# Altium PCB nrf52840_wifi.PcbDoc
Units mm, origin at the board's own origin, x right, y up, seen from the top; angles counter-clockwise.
Board outline 56.97 x 18.44 mm, 2 copper layers (Top Layer, Bottom Layer), stack 0.325 mm thick; 26 components, 63 nets, 152 pads, 96 vias.
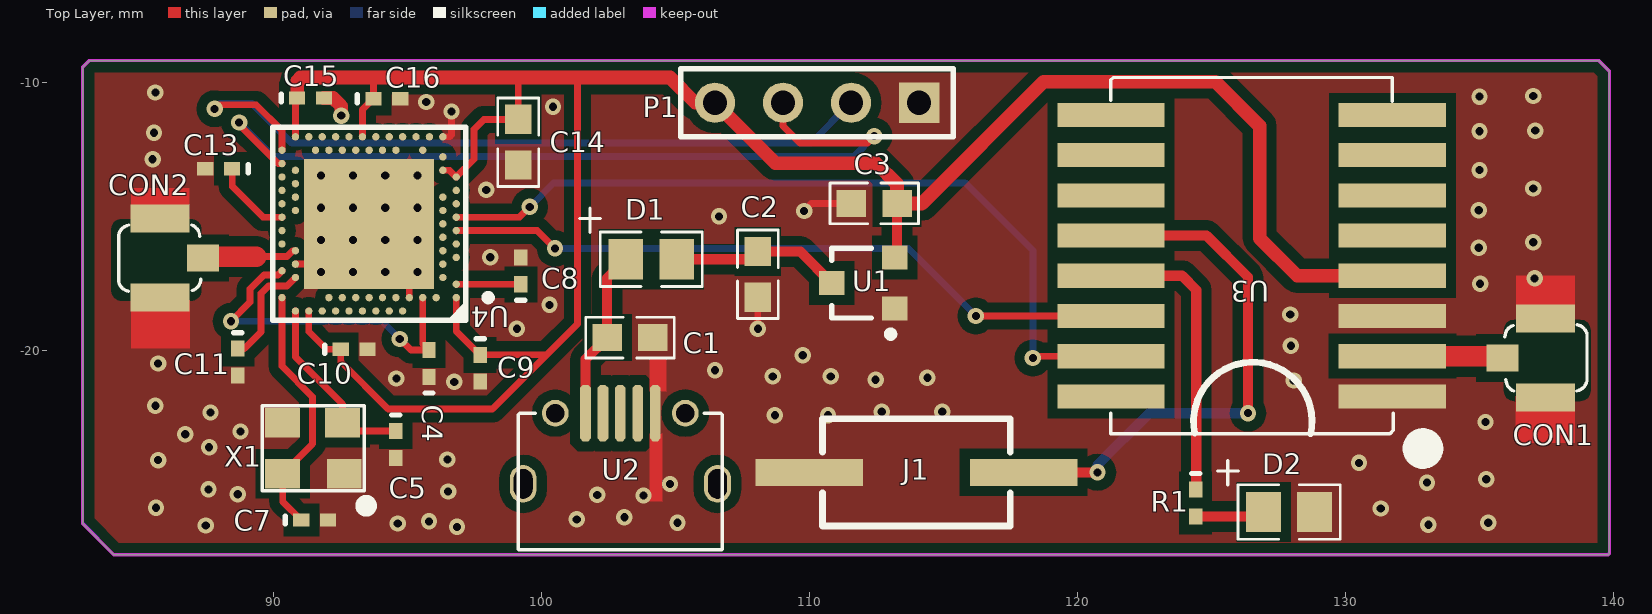
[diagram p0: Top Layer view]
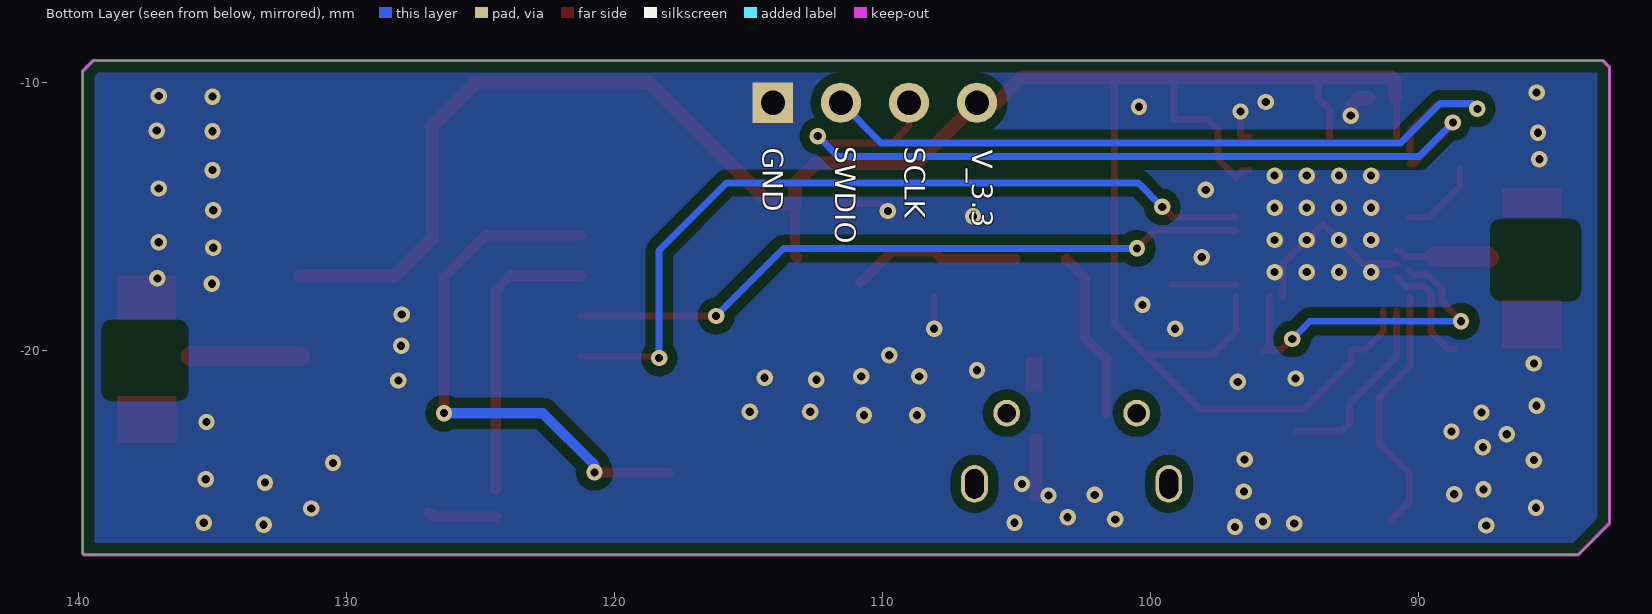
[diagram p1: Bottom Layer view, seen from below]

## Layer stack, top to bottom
Top Layer: signal copper 0.0356
Dielectric: core 0.254, FR-4, Dk 4.2
Bottom Layer: signal copper 0.0356

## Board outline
82.88,-26.441 82.88,-9.423 83.134,-9.169 139.446,-9.169 139.852,-9.576 139.852,-27.559 139.802,-27.61 84.049,-27.61

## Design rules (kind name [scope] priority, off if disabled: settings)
Clearance [All] p1: gap=0.152
ComponentClearance [All] p1 off: gap=0.254 collisioncheckmode=3 verticalgap=0.254 showdistances=FALSE
Height [All] p1 off: minheight=0 maxheight=25.4 prefheight=12.7
MinimumSolderMaskSliver [All] p1 off: minsoldermaskwidth=0.254
NetAntennae [All] p1 off: netantennaetolerance=0
PlaneConnect [All] p1: planeconnectstyle=Direct reliefexpansion=0.508 reliefentries=4 reliefconductorwidth=0.254 reliefairgap=0.254
PolygonConnect [All] p1: connectstyle=Direct reliefconductorwidth=0.254 reliefentries=4 polygonreliefangle="90 Angle"
RoutingVias [All] p1: holewidth=0.711 width=1.27 viastyle="Through Hole" minholewidth=0.711 minwidth=1.27 maxholewidth=0.711 maxwidth=1.27
SilkToSilkClearance [All] p1 off: silktosilkclearance=0.254
SilkscreenOverComponentPads SilkToSolderMaskClearance [IsPad] p1 off: minsilkscreentomaskgap=0.254
SolderMaskExpansion [All] p1: expansion=0.102
Width [All] p1: maxlimit=2.54 minlimit=0.025 preferedwidth=0.254 minimp=50.000000 maximp=50.000000 favimp=50.000000
21 further rules are at their usual default settings.

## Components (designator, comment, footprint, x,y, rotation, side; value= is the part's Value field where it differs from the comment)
C1 "2.2uF" 0603-1 103.302,-19.507 r0 top
C2 "1uF" 0603-1 108.077,-17.145 r270 top
C3 "1uF" 0603-1 112.42,-14.503 r180 top
C4 "1.0μF" 0402-A 95.809,-20.472 r90 top
C5 "12pF" 0402-A 94.564,-23.495 r270 top
C7 "12pF" 0402-A 91.542,-26.314 r0 top
C8 "100nF" 0402-A 99.238,-17.018 r90 top
C9 "1.0μF" 0402-A 97.714,-20.65 r270 top
C10 "100nF" 0402-A 93.015,-19.939 r0 top
C11 "100pF" 0402-A 88.671,-20.422 r270 top
C13 "820pF" 0402-A 87.96,-13.208 r180 top
C14 "4.7μF" 0603-1 99.136,-12.217 r270 top
C15 "100nF" 0402-a 91.389,-10.566 r0 top
C16 "100nF" 0402-a 94.234,-10.592 r0 top
CON1 "SMA/UFLR" IPX_U.FL 137.465,-20.269 r180 top
CON2 "SMA/UFLR" IPX_U.FL 85.776,-16.535 r0 top
D1 "Diode 1N4148" 0805-1 103.149,-16.586 r0 top
D2 "LED/RED" 0805-1 126.949,-26.01 r0 top
J1 "KEY" BUTTON_1 113.995,-24.536 r0 top
P1 "Header 4" HDR1X4 114.097,-10.744 r180 top
R1 "500R" 0402-a 124.409,-25.679 r270 top
U1 "MCP1703" SOT-23 112.014,-17.475 r90 top
U2 "USB_Micro" usb_micro 102.946,-22.327 r180 top
U3 "HC-25_wifi" HC-25 131.75,-11.201 r180 top
U4 "nRF52840-QIAA" AQFN50P700X700X85_HS-74N 93.574,-15.265 r180 top
X1 "32MHz" SMD3225 90.348,-24.587 r0 top

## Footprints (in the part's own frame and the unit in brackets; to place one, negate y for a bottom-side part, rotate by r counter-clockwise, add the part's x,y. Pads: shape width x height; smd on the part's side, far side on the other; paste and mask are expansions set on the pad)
0402-A [mm] "Chip Inductor; Body 1 x 0.5 mm (LxW typ)"
  rect 0.6x0.5 smd: 1(-0.5,0) 2(0.5,0)
  silkscreen extent -1.1,-0.15 -1.1,0.15
0402-a [mm] "Chip Inductor; Body 1 x 0.5 mm (LxW typ)"
  rect 0.6x0.5 smd: 1(-0.5,0) 2(0.5,0)
  silkscreen extent -1.1,-0.15 -1.1,0.15
0603-1 [mm]
  rect 1.1x1 smd: 1(-0.85,0) 2(0.85,0)
  silkscreen extent -1.65,-0.76 1.65,0.76, body extent -1.14,-0.38 1.14,0.38, height 1
0805-1 [mm]
  rect 1.3x1.5 smd: 1(0,0) 2(1.9,0)
  silkscreen extent -1.72,-1.02 2.85,1.91
AQFN50P700X700X85_HS-74N [mm]
  rect 4.85x4.85 smd mask+0.05: 74(0,0)
  round 0.275 smd paste+0.012 mask+0.05: A8(-1.25,3.25) A10(-0.75,3.25) A12(-0.25,3.25) A14(0.25,3.25) A16(0.75,3.25) A18(1.25,3.25) A20(1.75,3.25) A22(2.25,3.25) A23(2.75,3.25) AA24(3.25,-2.25) AB2(-2.75,-2.5) AC5(-2,-2.75) AC9(-1,-2.75) AC11(-0.5,-2.75) AC13(0,-2.75) AC15(0.5,-2.75) AC17(1,-2.75) AC19(1.5,-2.75) AC21(2,-2.75) AC24(3.25,-2.75) AD2(-2.75,-3.25) AD4(-2.25,-3.25) AD6(-1.75,-3.25) AD8(-1.25,-3.25) AD10(-0.75,-3.25) AD12(-0.25,-3.25) AD14(0.25,-3.25) AD16(0.75,-3.25) AD18(1.25,-3.25) AD20(1.75,-3.25) AD22(2.25,-3.25) AD23(2.75,-3.25) B1(-3.25,2.75) B3(-2.5,2.75) B5(-2,2.75) B7(-1.5,2.75) B9(-1,2.75) B11(-0.5,2.75) B13(0,2.75) B15(0.5,2.75) B17(1,2.75) B19(1.5,2.75) B24(3.25,2.75) C1(-3.25,2.25) D2(-2.75,2) D23(2.75,2) E24(3.25,1.75) F2(-2.75,1.5) F23(2.75,1.5) G1(-3.25,1.25) H2(-2.75,1) H23(2.75,1) J1(-3.25,0.75) J24(3.25,0.75) K2(-2.75,0.5) L1(-3.25,0.25) L24(3.25,0.25) M2(-2.75,0) N1(-3.25,-0.25) N24(3.25,-0.25) P2(-2.75,-0.5) P23(2.75,-0.5) R1(-3.25,-0.75) R24(3.25,-0.75) T2(-2.75,-1) T23(2.75,-1) U1(-3.25,-1.25) U24(3.25,-1.25) V23(2.75,-1.5) W1(-3.25,-1.75) W24(3.25,-1.75) Y2(-2.75,-2) Y23(2.75,-2)
  silkscreen extent -4.57,-3.6 3.6,3.6, body extent -3.55,-3.55 3.55,3.55, height 0.85
BUTTON_1 [mm]
  rect 4x1 smd: 1(-4,0) 2(4,0)
  silkscreen extent -3.5,-2 3.5,2
HC-25 [mm]
  rect 4x0.9 smd: 1(0,10.5) 2(0,9) 3(0,7.5) 4(0,6) 5(0,4.5) 6(0,3) 7(0,1.5) 8(0,0) 9(10.5,0) 10(10.5,1.5) 11(10.5,3) 12(10.5,4.5) 13(10.5,6) 14(10.5,7.5) 15(10.5,9) 16(10.5,10.5)
  silkscreen extent -1.5,-1.4 10.5,12.8
HDR1X4 [mm] "Connector; Header; 4 Position"
  rect 1.5x1.5 hole 0.9: 1(0,0)
  round 1.5 hole 0.9: 2(2.54,0) 3(5.08,0) 4(7.62,0)
  silkscreen extent -1.27,-1.27 8.89,1.27
IPX_U.FL [mm]
  rect 1.2x1 smd: 1(1.6,0)
  rect 2.2x1.05 smd: 2(0,-1.475) 3(0,1.475)
  silkscreen extent -1.55,-1.24 1.51,1.23
SMD3225 [mm]
  rect 1.3x1.1 smd: 1(0,0) 2(2.3,0) 3(2.23,1.9) 4(0,1.9)
  silkscreen extent -0.76,-1.32 3.24,2.54
SOT-23 [mm]
  rect 0.9x0.95 smd: 1(-0.95,-1.175) 2(0.95,-1.175) 3(0,1.175)
  silkscreen extent -2.03,-1.14 1.3,1.18
usb_micro [mm] "USB方?"
  oval 1x1.4 hole 0.7 slot 1.1 at 90 deg: 0(-3.625,2.638) 0(3.625,2.638)
  round 1 hole 0.7: 0(-2.425,0) 0(2.425,0)
  oct 0.4x2.1 smd: 1(1.3,0) 2(0.65,0) 3(0,0) 4(-0.65,0) 5(-1.3,0)
  silkscreen extent -3.81,0 3.81,5.1

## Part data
C1 C2 C3: library part CAP-0.1UF, "SMD-"
C4 C9: library part C0603-1?, "Capacitor, X7R, ±10%"
C5 C7: library part C0402-12p, "Capacitor, NP0, ±2%"
C8 C10 C15 C16: library part C0402-100n, "Capacitor, X7R, ±10%"
C11: library part C0402-100p, "Capacitor, NP0, ±5%"
C13: library part C0402-820p, "Capacitor, NP0, ±5%"
C14: library part C0603-4μ7-6.3, "Capacitor, X7R, ±10%"
D1: "High Conductance Fast Diode"
D2: library part LED/0603
P1: "Header, 4-Pin"
R1: library part R
U1: library part MCP170
U4: library part nRF52840-QIAAD0, "Multi-protocol Bluetooth Low Energy, IEEE 802.15.4, ANT and 2.4GHz proprietary system-on-chip"
X1: library part XTAL_SMD2016_32MHz_8pF_General, "XTAL SMD 2016, 32MHz, Cl=8pF, Total Tol: ±40ppm"

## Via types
v1: diameter 0.61, hole 0.305, Top Layer to Bottom Layer, 96 vias

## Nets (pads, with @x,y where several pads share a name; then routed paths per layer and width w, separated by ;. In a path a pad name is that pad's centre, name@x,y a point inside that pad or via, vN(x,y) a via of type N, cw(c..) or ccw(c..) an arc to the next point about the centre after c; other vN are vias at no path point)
DEC1: C8.1 U4.C1 | length 2.4
  Top Layer w0.254: U4.C1 C8.1@99.235,-17.515
DEC3: C11.1 U4.D23 | length 4.1
  Top Layer w0.254: C11.1 88.917,-19.922 89.535,-19.304 89.535,-17.856 89.814,-17.577 90.512,-17.577 U4.D23
DEC4_6: C4.2 U4.B5 U4.E24 | length 12.9
  Top Layer w0.254: v1(88.417,-18.898) 89.129,-18.186 89.129,-17.688 89.646,-17.17 90.169,-17.17 U4.E24 ; v1(94.717,-19.558) 95.131,-19.972 C4.2 95.574,-19.737 U4.B5
  Bottom Layer w0.254: v1(88.417,-18.898) 94.056,-18.898 v1(94.717,-19.558)
GND: C1.2 C2.2 C3.2 C4.1 C5.2 C7.2 C8.2 C9.2 C10.2 C11.2 C13.2 C14.2 C15.2 C16.2 CON1.2 CON1.3 CON2.2 CON2.3 D2.2 J1.1 P1.1 U1.1 U2.5 U3.1 U3.3 U4.74 U4.AD2 U4.B7 U4.F23 X1.2 X1.4 | length 12.2
  Top Layer w0.254: U4.F23 92.074,-16.765 v1(92.974,-15.865) U4.74 95.074,-16.765 U4.B7 ; U4.AD2 96.57,-12.015 96.647,-11.938 v1(96.647,-11.074) ; v1(108.077,-19.177) C2.2 ; v1(109.804,-14.783) 110.084,-14.503 C3.2
  Top Layer w0.508: C15.2 92.227,-10.566 92.532,-10.871 v1(92.532,-11.227)
  other v1: 96.85,-26.568 87.478,-26.518 133.096,-26.492 94.64,-26.441 105.08,-26.416 135.331,-26.416 95.809,-26.365 101.321,-26.289 103.099,-26.213 131.318,-25.883 85.623,-25.857 103.81,-25.4 102.083,-25.375 88.671,-25.349 96.52,-25.248 87.579,-25.171 104.8,-24.968 133.045,-24.917 135.255,-24.79 130.505,-24.181 85.7,-24.079 96.495,-24.054 87.605,-23.597 86.716,-23.114 88.773,-23.012 135.23,-22.657 108.712,-22.403 110.693,-22.403 87.655,-22.301 112.7,-22.276 114.96,-22.276 85.598,-22.047 96.749,-21.158 128.067,-21.107 112.471,-21.082 94.59,-21.031 114.402,-21.006 108.636,-20.955 110.795,-20.955 106.477,-20.726 85.7,-20.472 109.753,-20.168 127.965,-19.812 99.085,-19.177 127.94,-18.644 100.305,-18.288 135.026,-17.501 137.058,-17.297 91.774,-17.065 92.974,-17.065 94.174,-17.065 95.374,-17.065 98.095,-16.51 134.976,-16.154 137.008,-15.951 91.774,-15.865 94.174,-15.865 95.374,-15.865 106.629,-14.986 134.976,-14.757 91.774,-14.665 92.974,-14.665 94.174,-14.665 95.374,-14.665 97.942,-13.995 137.008,-13.945 91.774,-13.465 92.974,-13.465 94.174,-13.465 95.374,-13.465 135.001,-13.259 85.496,-12.852 85.547,-11.862 135.001,-11.811 137.084,-11.786 100.432,-10.897 95.707,-10.719 135.001,-10.516 137.008,-10.49 85.598,-10.363
NetC13_1: C13.1 U4.N24 | length 3
  Top Layer w0.254: C13.1@88.468,-13.225 88.468,-13.868 89.615,-15.015 U4.N24
NetCON1_1: CON1.1 U3.2 | length 4
  Top Layer w0.762: U3.2 CON1.1@135.797,-20.201
NetCON2_1: CON2.1 U4.H23 | length 3.6
  Top Layer w0.254: 89.357,-16.485 90.515,-16.485 90.734,-16.265 U4.H23
  Top Layer w0.762: CON2.1 87.427,-16.485 88.621,-16.485 89.357,-16.485
NetD2_1: D2.1 R1.2 | length 2.6
  Top Layer w0.381: R1.2 126.779,-26.179 D2.1
NetJ1_2: J1.2 U3.12 | length 20.3
  Top Layer w0.381: J1.2 v1(120.752,-24.536) ; U3.12 124.82,-15.701 126.365,-17.247 v1(126.365,-22.327)
  Bottom Layer w0.381: v1(120.752,-24.536) 120.752,-24.257 122.682,-22.327 v1(126.365,-22.327)
NetR1_1: R1.1 U3.13 | length 10.9
  Top Layer w0.381: U3.13 123.907,-17.201 124.435,-17.729 R1.1@124.435,-25.197
NRF52840_RX: U3.15 U4.N1 | length 30
  Top Layer w0.254: U4.N1 99.183,-15.015 v1(99.568,-14.63) ; v1(118.339,-20.269) 118.406,-20.201 U3.15
  Bottom Layer w0.254: v1(99.568,-14.63) 100.457,-13.741 115.824,-13.741 118.339,-16.256 v1(118.339,-20.269)
NRF52840_TX: U3.14 U4.L1 | length 25.7
  Top Layer w0.254: U4.L1 99.843,-15.515 v1(100.508,-16.18) ; v1(116.212,-18.701) U3.14
  Bottom Layer w0.254: v1(100.508,-16.18) 113.69,-16.18 v1(116.212,-18.701)
P0.02/AIN0: U4.A12
P0.03/AIN1: U4.B13
P0.04/AIN2: U4.J1
P0.05/AIN3: U4.K2
P0.07: U4.M2
P0.09/NFC1: U4.L24
P0.10/NFC2: U4.J24
P0.11: U4.T2
P0.12: U4.U1
P0.13: U4.AD8
P0.14: U4.AC9
P0.15: U4.AD10
P0.16: U4.AC11
P0.17: U4.AD12
P0.18/RESET: U4.AC13
P0.19: U4.AC15
P0.20: U4.AD16
P0.21: U4.AC17
P0.22: U4.AD18
P0.23: U4.AC19
P0.24: U4.AD20
P0.25: U4.AC21
P0.26: U4.G1
P0.27: U4.H2
P0.28/AIN4: U4.B11
P0.29/AIN5: U4.A10
P0.30/AIN6: U4.B9
P0.31/AIN7: U4.A8
P1.00: U4.AD22
P1.01: U4.Y23
P1.02: U4.W24
P1.03: U4.V23
P1.04: U4.U24
P1.05: U4.T23
P1.06: U4.R24
P1.07: U4.P23
P1.08: U4.P2
P1.09: U4.R1
P1.10: U4.A20
P1.11: U4.B19
P1.12: U4.B17
P1.13: U4.A16
P1.14: U4.B15
P1.15: U4.A14
SWDCLK: P1.3 U4.AA24 | length 31.5
  Top Layer w0.254: v1(88.722,-11.481) 88.722,-11.557 90.181,-13.015 U4.AA24 ; P1.3 109.017,-11.608 109.652,-12.243 112.166,-12.243 v1(112.42,-11.989)
  Bottom Layer w0.254: v1(88.722,-11.481) 89.992,-12.751 111.658,-12.751 v1(112.42,-11.989)
SWDIO: P1.2 U4.AC24 | length 28.8
  Top Layer w0.254: v1(87.808,-10.973) 87.96,-10.82 89.357,-10.82 90.324,-11.787 U4.AC24
  Bottom Layer w0.254: v1(87.808,-10.973) 88.011,-10.77 89.205,-10.77 90.678,-12.243 110.058,-12.243 P1.2
VBUS_5V: C1.1 D1.1 U2.1 | length 6.4
  Top Layer w0.381: U2.1 101.646,-20.313 C1.1 102.452,-17.284 D1.1
VCC_33: C3.1 C9.1 C10.1 C14.1 C15.1 C16.1 P1.4 U1.2 U3.4 U4.A22 U4.AD14 U4.AD23 U4.B1 U4.W1 U4.Y2 | length 90.9
  Top Layer w0.254: U4.AD23 90.824,-10.632 C15.1 ; U4.A22 91.324,-19.289 91.973,-19.939 C10.1 92.515,-20.404 94.285,-22.174 98.171,-22.174 100.195,-20.15 ; U4.AD14 93.324,-11.002 C16.1 93.734,-9.822 ; U4.Y2 96.574,-13.265 U4.W1 97.485,-12.854 97.485,-11.735 97.853,-11.367 C14.1 99.136,-9.855 ; U4.B1 96.824,-19.26 C9.1 100.195,-20.15 ; 101.321,-9.804 101.346,-9.83 101.346,-18.999 100.195,-20.15
  Top Layer w0.381: U1.2 113.27,-16.444 C3.1
  Top Layer w0.508: C15.1 90.889,-9.923 91.008,-9.804 101.321,-9.804 104.8,-9.804 105.74,-10.744 P1.4 108.737,-13.005 112.497,-13.005 113.27,-13.779 C3.1 114.198,-14.503 118.745,-9.957 125.146,-9.957 126.797,-11.608 126.797,-15.799 128.199,-17.201 U3.4
VCC_43: C2.1 D1.2 U1.3 | length 6.4
  Top Layer w0.381: D1.2 107.786,-16.586 C2.1 109.659,-16.295 U1.3
XC1: C7.1 U4.B24 X1.1 | length 9.5
  Top Layer w0.254: U4.B24 90.324,-20.575 91.465,-21.717 91.465,-23.47 X1.1 90.348,-25.621 C7.1
XC2: C5.1 U4.A23 X1.3 | length 7
  Top Layer w0.254: U4.A23 90.824,-20.237 92.578,-21.991 X1.3 92.886,-22.995 C5.1
pads on no net: U2.0 U2.2 U2.3 U2.4 U3.5 U3.6 U3.7 U3.8 U3.9 U3.10 U3.11 U3.16 U4.A18 U4.AB2 U4.AC5 U4.AD4 U4.AD6 U4.B3 U4.D2 U4.F2

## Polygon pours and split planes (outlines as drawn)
GND on Bottom Layer "Bottom Layer-No Net 1" (solid, remove dead copper, pour order 6): 81.051,-7.468 142.265,-7.468 143.154,-8.357 141.503,-10.008 141.503,-28.626 80.518,-28.626 80.289,-28.397
GND on Top Layer "Bottom Layer-No Net 1" (solid, remove dead copper, pour order 8): 81.534,-8.128 81.712,-7.95 141.503,-7.95 141.503,-27.483 140.106,-28.88 138.938,-30.048 79.553,-30.048

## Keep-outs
Keep-Out Layer:
  lines w0.127: 82.88,-26.441 82.88,-10.058 82.88,-9.423 83.134,-9.169 139.446,-9.169 139.852,-9.576 139.852,-9.931 139.852,-27.559 139.802,-27.61 139.294,-27.61 108.229,-27.61 84.049,-27.61 82.88,-26.441

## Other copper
Top Layer:
  rectangle net GND: 104.038,-21.514 104.673,-20.244
  rectangle net GND: 104.038,-25.629 104.521,-23.089
  rectangle net GND: 84.684,-19.914 86.893,-18.11
  rectangle net GND: 84.684,-15.011 86.868,-13.919
  rectangle net GND: 136.347,-23.444 138.557,-21.692
  rectangle net GND: 136.373,-18.847 138.557,-17.196

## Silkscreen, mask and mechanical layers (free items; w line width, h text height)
Bottom Overlay:
  text "SWDIO" at 111.76,-12.37 h0.76 r90
  text "SCLK" at 109.169,-12.395 h0.76 r90
  text "GND" at 114.478,-12.421 h0.76 r90
  text "V_3.3" at 106.655,-12.497 h0.76 r90
Top Solder:
  rectangle: -28,-2.159 -8.865,6.7
Bottom Solder:
  rectangle: -28,-2.159 -9.703,6.7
